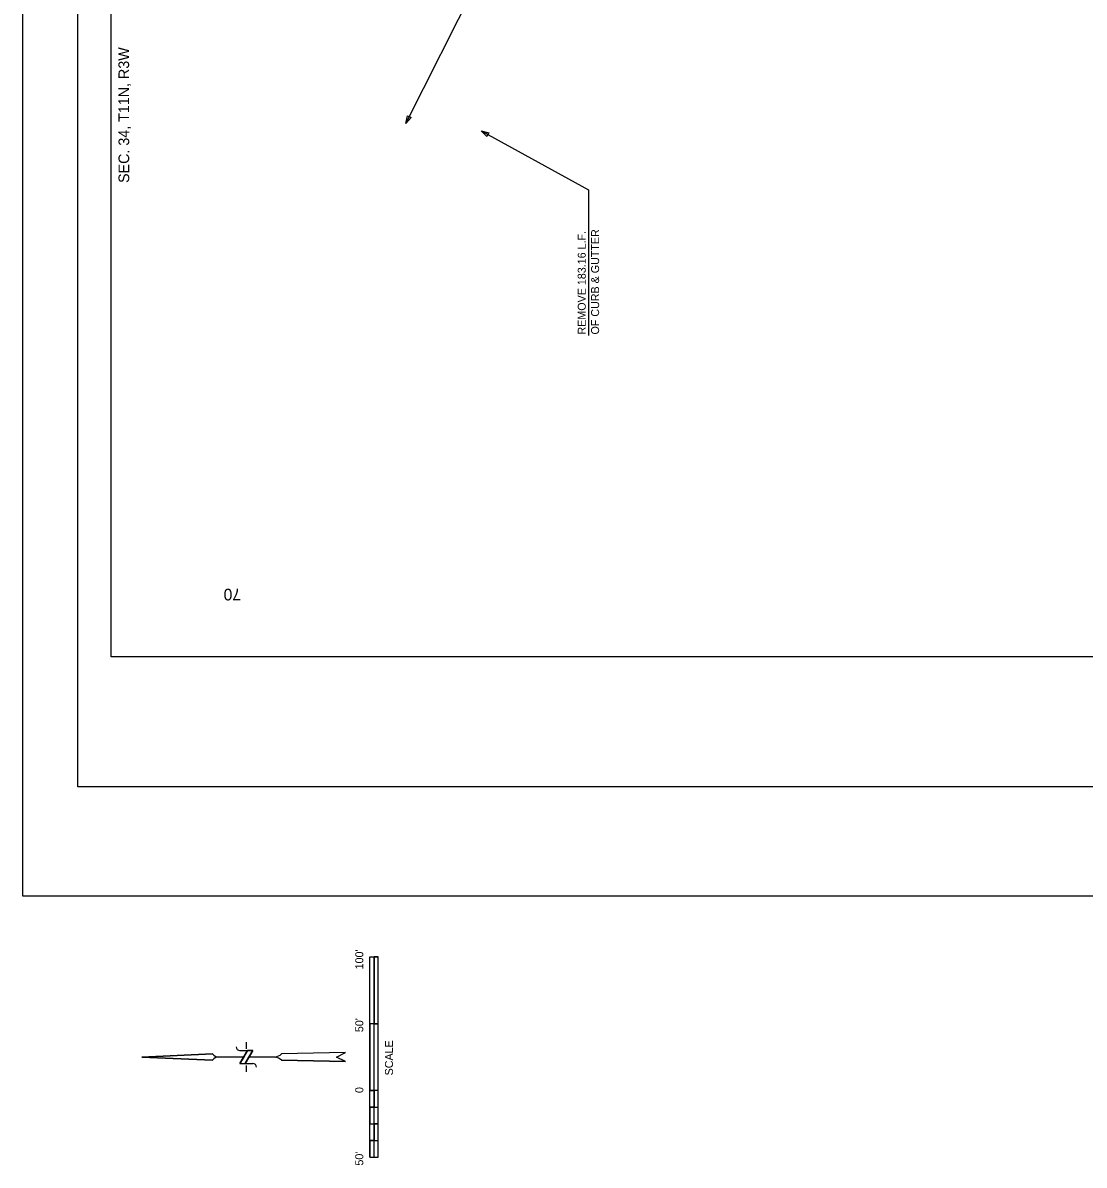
# Model space of a CAD drawing. Extents: x 2150645 to 2152288, y 141590 to 143592.
# Drawn here: x 2150645 to 2151440, y 141590 to 142447 of the extents above; entities that cross this region are included whole.
import ezdxf

# ---------------------------------------------------------------- set-up
doc = ezdxf.new("R2010")
doc.units = 0
for name, color, linetype in [('1', 7, 'Continuous'), ('EX_Align', 7, 'Continuous'), ('EX_Align_Sta', 7, 'Continuous'), ('INR_InRoads_Unassigned', 7, 'Continuous'), ('INR_Tracking', 7, 'Continuous'), ('PR_Align_Ramp_D', 7, 'Continuous'), ('TOPO_DRAIN_Headwall', 7, 'Continuous'), ('TOPO_San Manhole', 7, 'Continuous')]:
    doc.layers.add(name, color=color, linetype=linetype)

msp = doc.modelspace()

# ---------------------------------------------------------------- linework, layer by layer
at = {"layer": '1'}
for p, q in [((2150807.93, 141676.25), (2150817.52, 141676.25)), ((2150813.68, 141676.25), (2150807.93, 141666.65)), ((2150807.93, 141666.65), (2150813.68, 141676.25)), ((2150813.68, 141676.25), (2150810.8, 141671.45)), ((2150817.52, 141676.25), (2150811.76, 141666.65)), ((2150812.72, 141682.48), (2150812.72, 141677.69)), ((2150817.52, 141676.25), (2150813.68, 141676.25)), ((2150734.53, 141671.45), (2150787.41, 141673.85)), ((2150787.41, 141673.85), (2150734.53, 141671.45)), ((2150787.41, 141669.05), (2150734.53, 141671.45)), ((2150734.53, 141671.45), (2150787.41, 141669.05)), ((2150810.8, 141671.45), (2150792.09, 141671.45)), ((2150810.8, 141671.45), (2150807.93, 141666.65)), ((2150807.93, 141666.65), (2150817.52, 141666.65)), ((2150807.93, 141666.65), (2150811.76, 141666.65)), ((2150834.31, 141671.45), (2150814.64, 141671.45)), ((2150887.08, 141674.81), (2150839.11, 141673.85)), ((2150887.08, 141674.81), (2150839.11, 141673.85)), ((2150887.08, 141668.09), (2150839.11, 141669.05)), ((2150839.11, 141669.05), (2150887.08, 141668.09)), ((2150880.37, 141671.45), (2150887.08, 141674.81)), ((2150880.37, 141671.45), (2150887.08, 141674.81)), ((2150887.08, 141668.09), (2150880.37, 141671.45)), ((2150887.08, 141668.09), (2150880.37, 141671.45)), ((2150812.72, 141665.21), (2150812.72, 141660.42))]:
    msp.add_line(p, q, dxfattribs=at)
for points in [[(2150811.76, 141666.65), (2150814.64, 141671.45), (2150817.52, 141676.25)], [(2150834.31, 141671.46), (2150834.31, 141671.45), (2150834.31, 141671.44)]]:
    msp.add_lwpolyline(points, dxfattribs=at)
for centre, radius, start, end in [((2150807.93, 141679.13), 2.88, 180, 270), ((2150792.09, 141677.21), 5.76, 215.61984, 270), ((2150792.09, 141677.21), 5.76, 215.61984, 270), ((2150792.09, 141665.69), 5.76, 90, 144.38016), ((2150792.09, 141665.69), 5.76, 90, 144.38016), ((2150817.52, 141663.77), 2.88, 0, 90), ((2150833.15, 141679.8), 8.43, 277.58111, 315.04329), ((2150833.15, 141663.1), 8.43, 44.95671, 82.41889), ((2150833.15, 141679.8), 8.43, 277.941, 315.04329), ((2150833.15, 141663.1), 8.43, 44.95671, 82.059)]:
    msp.add_arc(centre, radius, start, end, dxfattribs=at)
at = {"layer": 'EX_Align'}
msp.add_lwpolyline([(2150645.33, 141792.07), (2150645.33, 143592.07), (2151845.33, 143592.07), (2151845.33, 141792.07)], close=True, dxfattribs=at)
at = {"layer": 'INR_Tracking'}
for p, q in [((2150905.33, 141746.45), (2150908.45, 141746.45)), ((2150905.33, 141596.45), (2150905.33, 141746.45)), ((2150908.45, 141746.45), (2150911.58, 141746.45)), ((2150908.45, 141646.45), (2150908.45, 141746.45)), ((2150911.58, 141746.45), (2150908.45, 141746.45)), ((2150908.45, 141746.45), (2150908.45, 141696.45)), ((2150911.58, 141596.45), (2150911.58, 141746.45)), ((2150911.58, 141696.45), (2150911.58, 141746.45)), ((2150908.45, 141696.45), (2150905.33, 141696.45)), ((2150908.45, 141696.45), (2150905.33, 141696.45)), ((2150905.33, 141696.45), (2150905.33, 141646.45)), ((2150911.58, 141696.45), (2150908.45, 141696.45)), ((2150908.45, 141646.45), (2150908.45, 141696.45)), ((2150908.45, 141696.45), (2150911.58, 141696.45)), ((2150908.45, 141646.45), (2150905.33, 141646.45)), ((2150905.33, 141646.45), (2150908.45, 141646.45)), ((2150911.58, 141646.45), (2150908.45, 141646.45)), ((2150908.45, 141633.95), (2150908.45, 141646.45)), ((2150911.58, 141646.45), (2150908.45, 141646.45)), ((2150908.45, 141646.45), (2150908.45, 141633.95)), ((2150911.58, 141633.95), (2150911.58, 141646.45)), ((2150905.33, 141633.95), (2150911.58, 141633.95)), ((2150908.45, 141633.95), (2150905.33, 141633.95)), ((2150905.33, 141633.95), (2150905.33, 141621.45)), ((2150908.45, 141621.45), (2150908.45, 141633.95)), ((2150908.45, 141621.45), (2150908.45, 141633.95)), ((2150908.45, 141633.95), (2150911.58, 141633.95)), ((2150905.33, 141621.45), (2150911.58, 141621.45)), ((2150905.33, 141621.45), (2150911.58, 141621.45)), ((2150905.33, 141621.45), (2150908.45, 141621.45)), ((2150908.45, 141608.95), (2150908.45, 141621.45)), ((2150911.58, 141621.45), (2150908.45, 141621.45)), ((2150908.45, 141621.45), (2150908.45, 141608.95)), ((2150911.58, 141608.95), (2150911.58, 141621.45)), ((2150905.33, 141608.95), (2150911.58, 141608.95)), ((2150908.45, 141608.95), (2150905.33, 141608.95)), ((2150905.33, 141608.95), (2150905.33, 141596.45)), ((2150908.45, 141596.45), (2150908.45, 141608.95)), ((2150908.45, 141596.45), (2150908.45, 141608.95)), ((2150908.45, 141608.95), (2150911.58, 141608.95)), ((2150905.33, 141596.45), (2150911.58, 141596.45)), ((2150905.33, 141596.45), (2150908.45, 141596.45))]:
    msp.add_line(p, q, dxfattribs=at)
at = {"layer": 'PR_Align_Ramp_D'}
msp.add_lwpolyline([(2151761.58, 143546.45), (2151761.58, 141971.45), (2150711.58, 141971.45), (2150711.58, 143546.45)], close=True, dxfattribs=at)
at = {"layer": 'TOPO_DRAIN_Headwall'}
msp.add_lwpolyline([(2150686.58, 141873.95), (2150686.58, 143573.95), (2151786.58, 143573.95), (2151786.58, 141873.95)], close=True, dxfattribs=at)
at = {"layer": 'TOPO_San Manhole'}
msp.add_line((2151068.96, 142315.4), (2151068.96, 142212.21), dxfattribs=at)
for points in [[(2150932.15, 142371.03), (2150984.94, 142475.73), (2150984.94, 142481.73)], [(2150988.59, 142365.57), (2151068.96, 142321.4), (2151068.96, 142315.4)]]:
    msp.add_lwpolyline(points, dxfattribs=at)
for points in [[(2150932.15, 142371.03), (2150933.47, 142376.89), (2150936.07, 142375.57)], [(2150988.59, 142365.57), (2150994.4, 142364.04), (2150992.99, 142361.49)]]:
    msp.add_lwpolyline(points, close=True, dxfattribs=at)

# ---------------------------------------------------------------- texts
at = {"layer": 'EX_Align_Sta'}
msp.add_text('70', height=8.75, rotation=180.50149, dxfattribs=at).set_placement((2150808.69, 142022.53))
at = {"layer": 'INR_InRoads_Unassigned'}
msp.add_text('SEC. 34, T11N, R3W', height=8, rotation=90.02698, dxfattribs=at).set_placement((2150724.98, 142326.57))
at = {"layer": 'INR_Tracking'}
for s, p in [("100'", (2150900.33, 141737.15)), ("50'", (2150900.33, 141690.09)), ('SCALE', (2150922.58, 141657.69)), ('0', (2150900.33, 141644.48)), ("50'", (2150900.33, 141590.09))]:
    msp.add_text(s, height=6, rotation=90, dxfattribs=at).set_placement(p)
at = {"layer": 'TOPO_San Manhole'}
for s, p in [('REMOVE 183.16 L.F.', (2151066.96, 142212.97)), ('OF CURB & GUTTER', (2151076.96, 142212.97))]:
    msp.add_text(s, height=6, rotation=90, dxfattribs=at).set_placement(p)

doc.saveas('drawing.dxf')
